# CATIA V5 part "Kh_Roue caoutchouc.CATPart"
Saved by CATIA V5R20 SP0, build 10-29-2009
Part number: Roue caoutchouc
Bounding box of the stored display mesh (mm): x -55.995 to 55.995, y -29 to 29, z -55.995 to 55.995
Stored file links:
  G:\Khaled_CFAO_2011\SIL\SIL_GR1\tmerino\Khaled\CAD_Thinkmotion\Kh_Roue caoutchouc.CATPart
  G:\Khaled_CFAO_2011\SIL\SIL_GR1\tmerino\Khaled\CAD_Thinkmotion\Kh_Catalog.CATMaterial
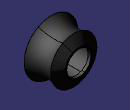
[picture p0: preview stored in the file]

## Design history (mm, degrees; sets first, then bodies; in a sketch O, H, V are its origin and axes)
Set1 "Plan"
  Plane1: type Offset, RefPlane zx-plane, Offset 0
  Sketch1 on Plane1, origin (0, 0, 0), H (-1, 0, 0), V (0, 0, 1)
    circle A1 centre (0, 0) radius 41.3585
    radius A1 = 41.3585
  Sketch2 on Plane1, origin (0, 0, 0), H (-1, 0, 0), V (0, 0, 1)
    circle A1 centre (0, 0) radius 41.7055
    radius A1 = 41.7055
Body1 (main body), material "Caoutchouc"
  Sketch3 on yz-plane, origin (0, 0, 0), H (0, 1, 0), V (0, 0, 1)
    line L1 (-29, -56) -> (-29, -42)
    point P3 (29, 90)
    line L2 (-29, -42) -> (-23, -42)
    line L3 (-23, -42) -> (-23, -34)
    line L4 (-23, -34) -> (23, -34)
    line L5 (23, -34) -> (23, -25)
    line L6 (23, -25) -> (29, -25)
    line L7 (29, -25) -> (29, -56)
    arc A1 centre (0, -83.55) radius 40 from (29, -56) to (-29, -56) ccw
    distance V L1 = 29
    length L1 = 14
    length L2 = 6
    length L3 = 8
    length L4 = 46
    length L5 = 9
    length L6 = 6
    vertical: L1 V, L3 V, L5 V, L7 V
    horizontal: L2 H, L4 H, L6 H
    fix: A1
  Shaft1: profile Sketch3, axis Sketch3.H, angle 360
  Sketch4 on face of Shaft1 from Sketch3.L3, origin (11.6205, -23, -36.2849), H (1, 0, 0), V (0, 0, 1)
    point P1 (26.3795, 36.2849)
    reference intersected line E1 through (0, 36.2849) direction (-1, 0) from xy-plane
    reference intersected line E2 through (-11.6205, 0) direction (0, 1) from yz-plane
    distance E1 P1 = 0
    distance E2 P1 = 38
  Hole1: placed by Sketch4, at (38, -23, 0) direction (0, 1, 0), diameter 3.5, depth 10, threaded, thread diameter 4, thread depth 10, pitch 1
  CircPattern1: of Hole1, instances 9, angular step 40, axis from face of Shaft1 from Sketch3.L4
  Chamfer1: length 12, angle 89, on edge [face of Shaft1 from Sketch3.A1 | face of Shaft1 from Sketch3.L7]
  Sketch5 on zx-plane, origin (0, 0, 0), H (-1, 0, 0), V (0, 0, 1)
    circle A1 centre (0, 0) radius 41.3586
    point P1 (43.55, 0)
    radius A1 = 41.3586 (reference)
    radius A1 = 41.3586 (reference)
    radius A1 = 41.3586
